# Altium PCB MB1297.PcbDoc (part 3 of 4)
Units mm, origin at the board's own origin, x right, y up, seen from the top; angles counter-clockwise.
Board outline 90.1 x 62.11 mm, 4 copper layers (Top Layer, GND, POWER+GND, Bottom Layer), stack 0.778 mm thick; 235 components, 175 nets, 1727 pads, 1 vias.
Unrouted connection lines stored in the file: 1.
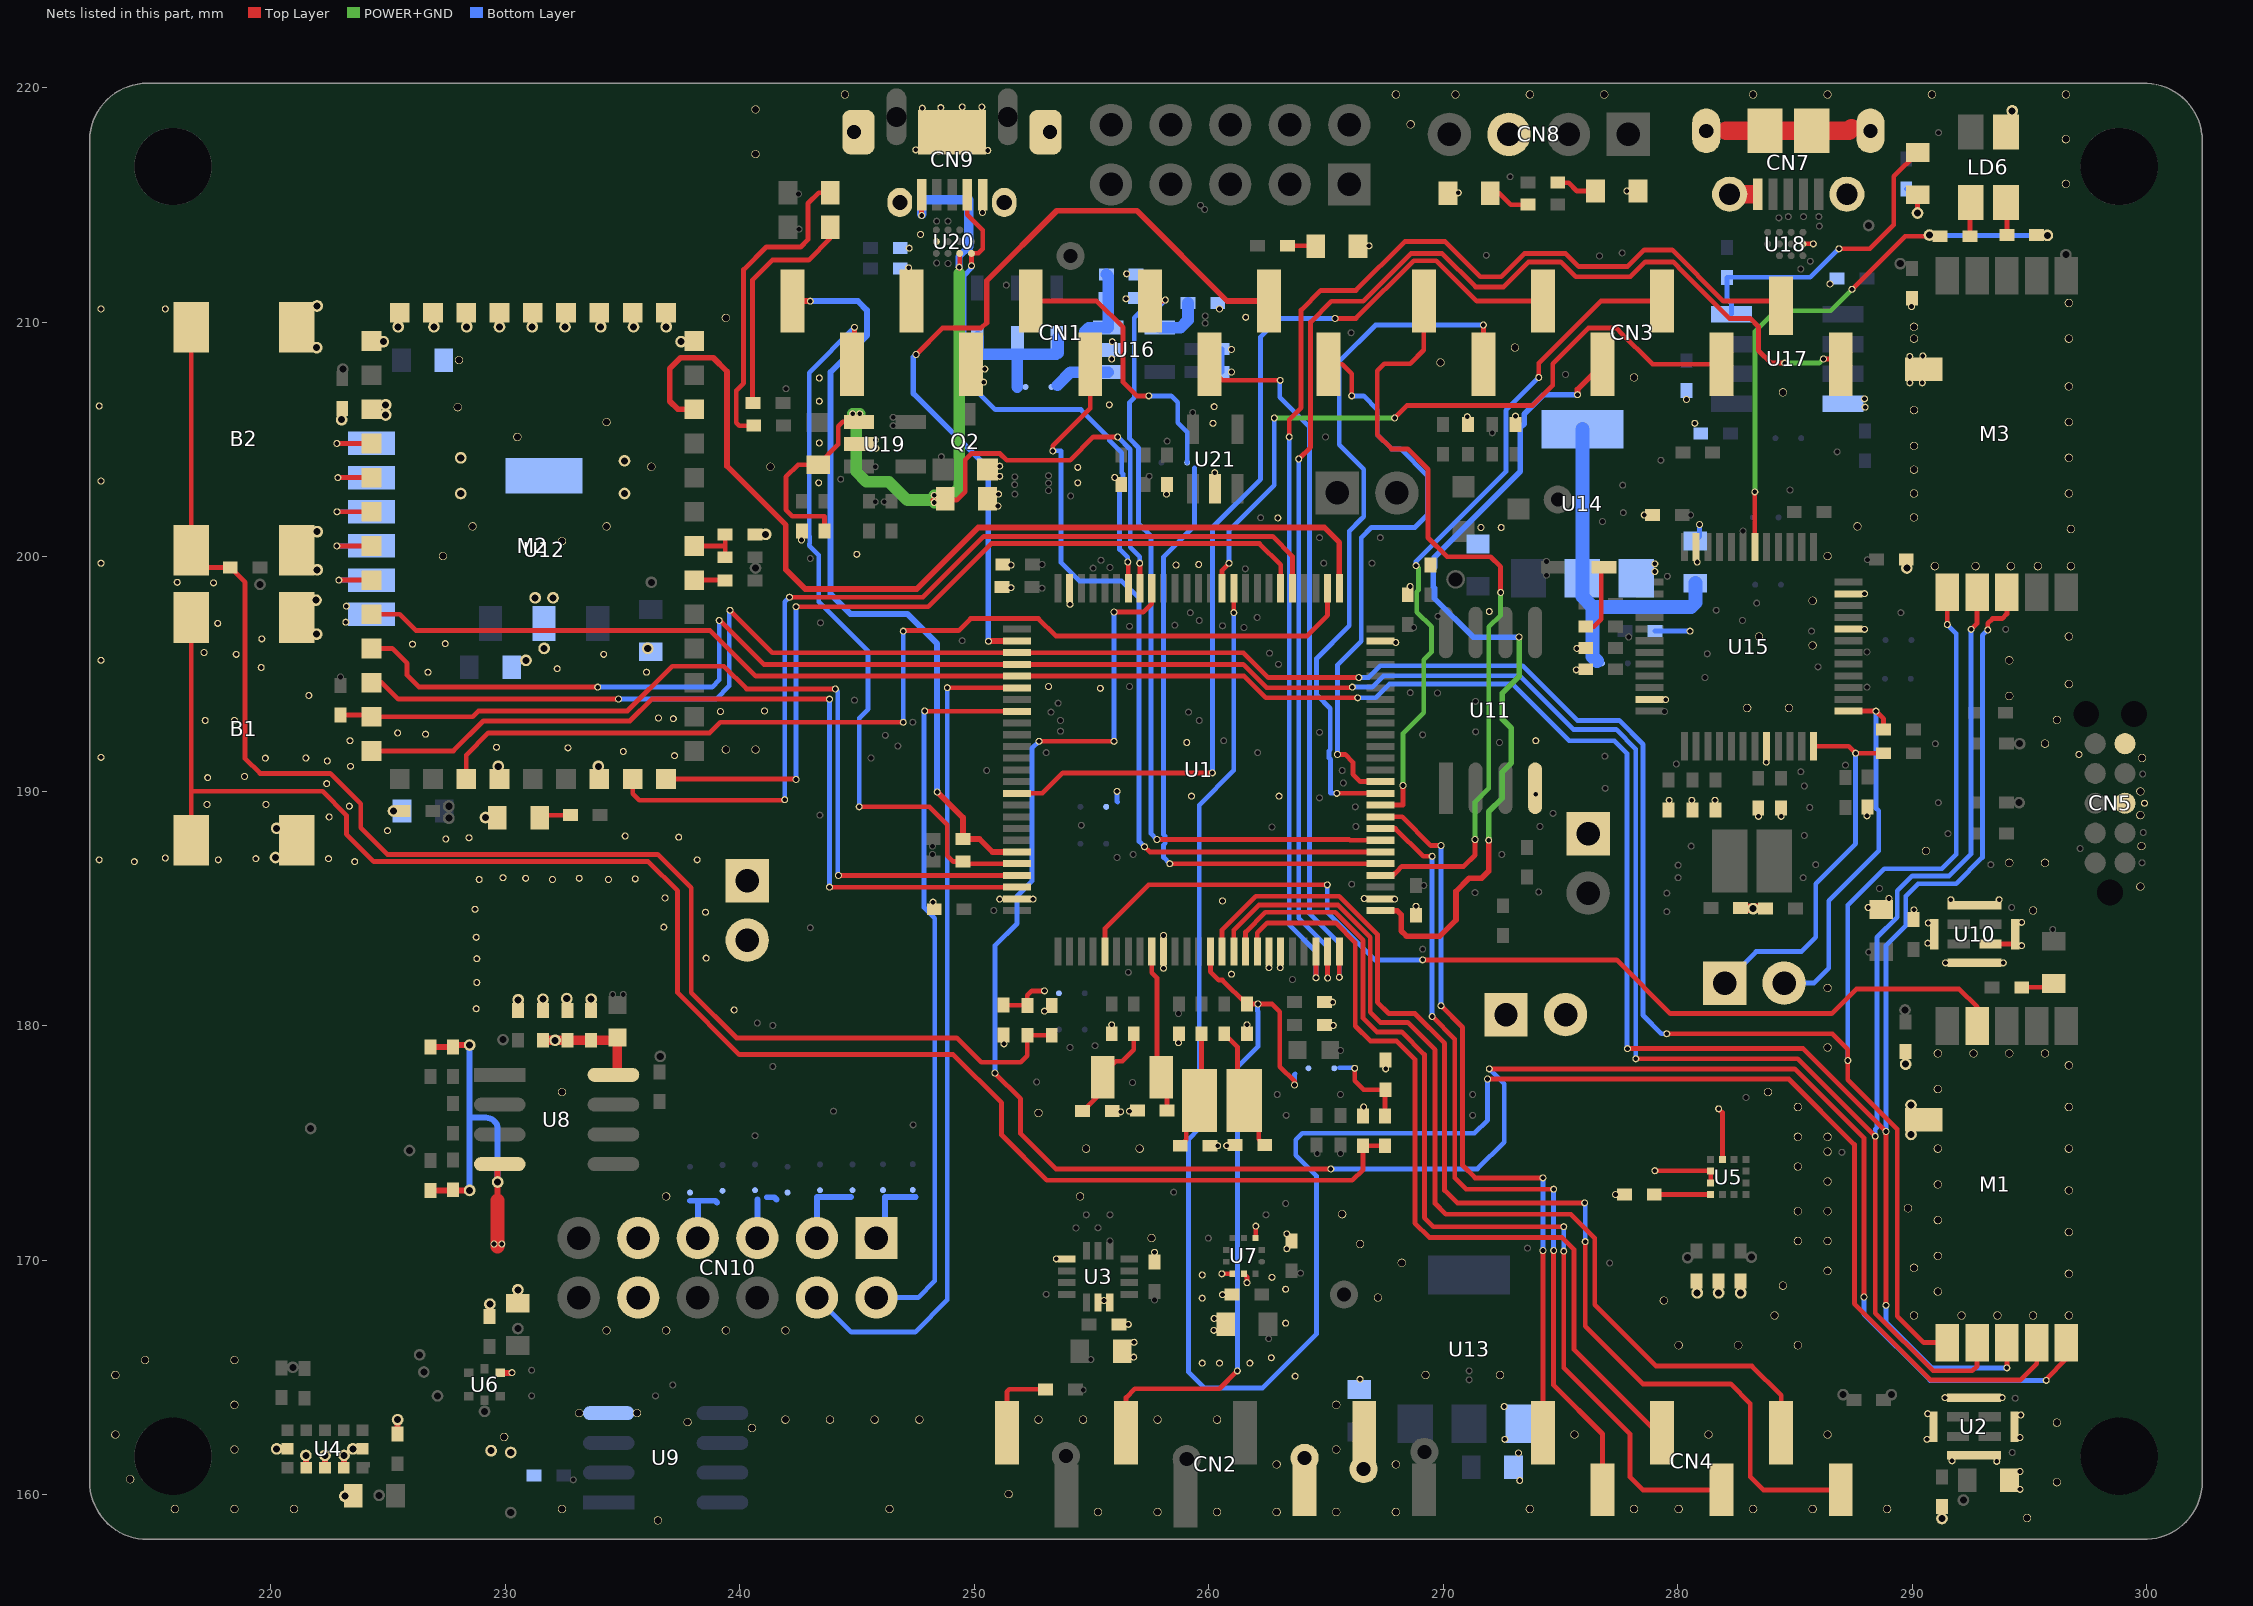
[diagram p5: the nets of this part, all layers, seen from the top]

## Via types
v1: diameter 0.4, hole 0.2, Top Layer to Bottom Layer, tented both sides, 1 vias

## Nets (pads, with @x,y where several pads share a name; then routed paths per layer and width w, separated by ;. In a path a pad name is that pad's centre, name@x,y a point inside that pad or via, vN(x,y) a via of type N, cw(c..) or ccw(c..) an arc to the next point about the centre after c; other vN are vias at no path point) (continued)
GND: B1.2 B2.2 C1.2 C2.2 C3.1 C4.2 C5.2 C6.1 C7.2 C8.1 C9.2 C10.2 C11.2 C12.2 C13.2 C14.2 C15.2 C16.2 C17.1 C18.2 C19.2 C20.2 C21.2 C22.2 C23.2 C24.2 C25.2 C26.2 C27.2 C28.2 C29.2 C30.2 C31.2 C32.2 C33.2 C34.2 C35.2 C36.2 C37.2 C38.2 C39.2 C40.2 C41.2 C42.2 C43.2 C44.2 C45.2 C46.2 C47.2 C48.2 C49.2 C50.2 C51.1 C52.1 C53.2 C54.2 C55.2 C56.2 C57.2 C58.2 C59.2 C60.2 C61.2 C62.2 C63.2 C64.2 C65.2 C66.2 C67.2 C68.2 C69.2 C71.2 C72.2 C73.2 C74.2 C75.2 C76.2 CN1.7 CN2.6 CN2.7 CN5.3 CN5.5 CN7.5 CN7.6 CN7.7 CN7.8 CN7.9 CN7.10 CN7.11 CN8.3 CN9.5 CN9.6 CN9.7 CN9.8 CN9.9 CN9.10 CN10.5 CN10.11 JP6.1 JP6.2 JP7.1 JP7.2 JP8.1 LD1.K LD2.K LD3.K LD5.K LD6.1 M1.6 M2.1 M2.3 M2.17 M2.20 M2.35 M2.36 M2.37 M2.38 M2.39 M2.40 M2.41 M2.42 M2.43 M2.44 M3.6 pad.0@212.75,210.566 pad.0@229.387,161.874 pad.1@215.494,210.566 pad.1@230.226,161.798 pad.2@212.674,187.071 pad.2@229.337,168.123 pad.2@230.53,168.732 pad.3@215.494,187.147 pad.3@229.146,188.874 pad.4@214.173,186.995 pad.5@212.75,191.44 pad.5@223.152,159.931 pad.5@279.476,193.904 pad.6@212.75,195.58 pad.6@223.215,197.891 pad.6@231.648,196.088 pad.6@287.96,198.425 pad.7@212.75,199.72 pad.7@223.19,197.206 pad.7@223.491,161.95 pad.7@231.267,198.247 pad.7@287.96,196.901 pad.8@212.75,203.225 pad.8@223.114,161.671 pad.8@232.029,198.247 pad.8@247.701,213.741 pad.8@283.769,191.237 pad.9@212.674,206.426 pad.9@222.301,161.671 pad.9@228.092,204.216 pad.10@217.551,198.882 pad.10@221.488,161.671 pad.10@228.092,202.692 pad.10@280.822,199.771 pad.11@216.002,198.907 pad.11@220.243,161.95 pad.11@235.077,204.089 pad.11@278.562,201.778 pad.12@217.729,197.155 pad.12@225.4,163.195 pad.12@235.077,202.692 pad.13@217.297,190.576 pad.14@218.872,190.627 pad.15@217.195,193.015 pad.15@275.692,196.088 pad.15@285.776,213.34 pad.16@218.44,193.015 pad.16@224.79,209.169 pad.16@275.666,195.174 pad.17@217.145,195.91 pad.17@225.425,209.804 pad.18@218.516,195.834 pad.18@226.949,209.804 pad.19@222.377,190.322 pad.19@228.346,209.804 pad.19@289.966,210.668 pad.20@223.342,189.357 pad.20@229.743,209.804 pad.21@217.754,187.071 pad.21@231.14,209.804 pad.22@219.354,187.122 pad.22@232.537,209.804 pad.23@217.272,189.433 pad.23@234.061,209.804 pad.24@219.786,189.433 pad.24@228.473,179.172 pad.24@235.458,209.804 pad.25@222.479,188.9 pad.25@228.473,172.974 pad.25@236.855,209.804 pad.26@222.453,187.122 pad.26@229.667,173.33 pad.26@237.49,209.169 pad.27@223.571,186.995 pad.27@230.543,181.102 pad.28@228.879,186.233 pad.28@231.597,181.127 pad.28@241.097,200.952 pad.29@228.752,180.721 pad.29@232.613,181.153 pad.29@247.218,213.157 pad.30@228.778,181.839 pad.30@233.655,181.127 pad.31@228.778,182.855 pad.32@228.752,183.769 pad.33@228.702,184.963 pad.34@229.895,186.309 pad.35@230.861,186.284 pad.36@232.004,186.233 pad.37@233.147,186.284 pad.37@260.553,169.418 pad.38@234.391,186.233 pad.38@261.62,169.037 pad.39@235.534,186.258 pad.39@291.262,158.979 pad.40@236.753,184.201 pad.41@236.804,185.445 pad.41@262.001,171.45 pad.42@224.968,188.316 pad.43@227.457,187.96 pad.43@260.579,168.529 pad.44@228.448,188.011 pad.44@260.223,167.513 pad.45@235.102,188.087 pad.45@260.21,167.005 pad.45@266.598,176.53 pad.45@299.898,189.484 pad.46@237.388,188.036 pad.46@267.538,178.156 pad.46@297.104,191.567 pad.47@238.176,187.071 pad.48@238.531,184.836 pad.48@264.083,161.568 pad.48@266.597,161.086 pad.49@238.557,182.88 pad.50@239.751,180.67 pad.50@256.807,166.497 pad.51@229.616,191.872 pad.51@256.794,165.862 pad.52@232.664,191.846 pad.52@256.565,167.259 pad.53@235.026,191.694 pad.54@237.211,191.516 pad.54@257.683,170.332 pad.55@236.525,193.116 pad.55@255.524,168.275 pad.55@256.083,189.992 pad.56@230.276,165.202 pad.56@237.16,193.091 pad.56@289.941,176.606 pad.57@229.845,170.688 pad.57@239.166,193.396 pad.57@253.492,170.053 pad.57@289.941,175.362 pad.58@229.514,170.688 pad.58@241.046,193.421 pad.58@289.712,178.359 pad.59@236.017,195.072 pad.59@266.827,213.258 pad.59@289.89,208.534 pad.60@232.207,195.224 pad.60@290.449,208.559 pad.61@234.188,195.834 pad.61@266.624,185.42 pad.61@289.89,207.416 pad.62@226.695,195.072 pad.62@267.919,185.395 pad.62@290.424,207.416 pad.63@227.432,196.291 pad.63@268.834,185.09 pad.63@280.365,206.705 pad.64@226.035,196.266 pad.64@256.489,212.065 pad.64@273.939,192.151 pad.64@280.721,205.689 pad.65@219.761,191.409 pad.65@256.464,210.998 pad.65@273.939,189.865 pad.65@287.96,206.731 pad.66 pad.67@221.615,194.081 pad.67@260.96,207.874 pad.68@219.583,195.275 pad.69@219.608,196.494 pad.69@262.56,182.474 pad.69@267.97,196.342 pad.70@222.402,191.287 pad.70@272.618,162.357 pad.70@280.822,168.605 pad.71@223.393,191.059 pad.71@272.593,163.754 pad.71@281.737,168.605 pad.72@223.368,192.151 pad.72@273.202,161.773 pad.72@282.677,168.605 pad.73@225.4,192.481 pad.73@273.253,160.604 pad.74@226.593,192.43 pad.74@272.466,201.244 pad.75@255.372,194.386 pad.75@271.602,201.244 pad.76@253.162,194.462 pad.76@288.112,185.039 pad.77@289.001,185.42 pad.78@290.068,184.937 pad.80@290.678,184.379 pad.81@289.763,199.517 pad.81@290.659,183.515 pad.82@247.777,219.126 pad.82@283.21,184.988 pad.82@291.643,185.369 pad.83@248.564,219.151 pad.83@293.7,185.369 pad.84@223.012,205.842 pad.84@250.317,219.177 pad.84@294.659,184.404 pad.85@224.892,206.477 pad.85@250.571,217.322 pad.85@294.659,183.413 pad.86@224.892,206.045 pad.86@247.498,217.348 pad.86@291.414,182.677 pad.87@249.479,219.177 pad.87@293.878,182.677 pad.88@230.873,195.58 pad.88@250.342,214.681 pad.89@236.068,196.088 pad.89@250.444,208.001 pad.89@291.389,164.135 pad.90@250.393,207.442 pad.90@293.827,164.135 pad.91@225.222,189.154 pad.91@279.019,173.812 pad.91@294.625,163.398 pad.92@229.692,191.059 pad.92@281.737,176.454 pad.92@294.589,162.433 pad.93@233.959,191.059 pad.93@251.257,179.222 pad.94@220.243,188.417 pad.94@252.984,180.619 pad.95@220.193,187.173 pad.95@290.652,163.449 pad.96 pad.97@221.945,196.698 pad.97@254.076,197.968 pad.97@291.694,161.442 pad.98 pad.99@221.971,199.441 pad.99@294.589,160.985 pad.100 pad.101@221.945,208.915 pad.101@266.446,164.922 pad.105@263.271,168.758 pad.106@263.271,167.31 pad.106@288.061,188.951 pad.107@262.687,169.266 pad.107@283.439,188.925 pad.107@294.259,219.011 pad.108@259.715,169.367 pad.108@284.404,188.925 pad.109@259.715,168.377 pad.109@281.584,189.611 pad.110@259.715,165.608 pad.110@280.594,189.611 pad.111@260.452,165.608 pad.111@279.629,189.611 pad.112@258.064,183.845 pad.112@261.747,165.608 pad.113@258.064,182.448 pad.113@262.661,165.837 pad.114 pad.115@260.96,182.194 pad.115@265.278,181 pad.116@260.579,185.318 pad.116@265.303,180.01 pad.117@262.992,189.789 pad.118 pad.119 pad.120 pad.121@255.854,180.035 pad.121@259.563,199.669 pad.122 pad.123 pad.124 pad.125 pad.126@260.172,205.689 pad.126@270.637,215.519 pad.127 pad.128@251.562,198.679 pad.128@261.569,210.21 pad.129@243.383,207.62 pad.130@243.383,206.629 pad.131@243.383,204.851 pad.132@243.357,203.149 pad.133@244.983,200.101 pad.136@251.079,185.395 pad.137@252.501,185.395 pad.142 pad.143@268.58,198.73 pad.149@277.343,172.796 pad.173 pad.175 pad.217 pad.218 pad.219 pad.222 pad.225 pad.226 pad.231 pad.232 pad.233 pad.234 pad.235 pad.236 pad.237 pad.249 pad.250 pad.251 pad.252 pad.253 pad.254 pad.255 pad.256 pad.257 pad.258 pad.259 pad.260 pad.261 pad.262 pad.263 pad.264 pad.265 pad.266 pad.267 pad.268 pad.269 pad.270 pad.271 pad.272 pad.273 pad.274 pad.275 pad.276 pad.277 pad.278 pad.279 pad.280 pad.281 pad.282 pad.283 pad.284 pad.285 pad.286 pad.287 pad.288 pad.289 pad.290 pad.291 pad.292 pad.293 pad.294 pad.295 pad.296 pad.297 pad.298 pad.299 pad.300 pad.301 pad.302 pad.303 pad.304 pad.305 pad.306 pad.307 pad.308 pad.309 pad.310 pad.311 pad.312 pad.313 pad.314 pad.315 pad.316 pad.317 pad.318 pad.319 pad.320 pad.321 pad.322 pad.327 pad.328 pad.329 pad.330 pad.331 pad.332 pad.333 pad.334 pad.335 pad.336 pad.337 pad.338 pad.339 pad.340 pad.341 pad.342 pad.343 pad.344 pad.345 pad.346 pad.347 pad.348 pad.349 pad.350 pad.351 pad.352 pad.353 pad.354 pad.355 pad.356 pad.357 pad.358 pad.359 pad.360 pad.361 pad.362 pad.363 pad.364 pad.365 pad.366 pad.367 pad.368 pad.369 pad.370 pad.371 pad.372 pad.373 pad.374 pad.375 pad.376 pad.377 pad.378 pad.379 pad.380 pad.381 pad.382 pad.383 pad.384 pad.385 pad.386 pad.387 pad.388 pad.389 pad.390 pad.391 pad.392 pad.393 pad.394 pad.395 pad.396 pad.397 pad.398 pad.399 pad.400 pad.401 pad.402 pad.403 pad.404 pad.405 pad.406 pad.407 pad.408 pad.409 pad.410 pad.411 pad.412 pad.413 pad.414 pad.415 pad.416 pad.417 pad.418 pad.420 pad.421 pad.422 pad.423 pad.424 pad.425 pad.426 pad.427 pad.428 pad.429 pad.430 pad.431 pad.432 pad.433 pad.434 Q2.2 R1.1 R27.2 R29.2 R31.2 R36.2 R38.1 R41.2 R46.1 R53.1 R54.2 R59.1 R64.2 SB13.1 TP6.1 U1.10 U1.19 U1.20 U1.27 U1.49 U1.74 U1.99 U2.5 U3.1 U3.6 U3.7 U4.2 U4.3 U4.4 U4.6 U4.12 U5.2 U5.3 U5.12 U6.5 U7.3 U7.8 U7.9 U8.4 U9.4 U10.2 U10.5 U11.4 U12.2 U13.1 U14.1 U15.8 U15.20 U15.23 U15.35 U15.47 U16.2 U17.4 U18.D2 U19.2 U20.D2 U21.2 | length 39.4
  Top Layer w0.2: U10.2@293.334,183.481 294.318,183.481 294.361,183.439 U10.5@294.361,183.481
  Top Layer w0.204: pad.37@260.553,169.418 U7.8@260.993,169.417 ; U7.9@261.493,169.417 261.62,169.29 pad.38@261.62,169.037 ; U7.3@261.993,170.943 pad.41@261.993,171.442 ; pad.91@279.019,173.812 281.397,173.812 U5.3@281.397,173.295 ; pad.92@281.737,176.454 281.897,176.293 U5.12@281.897,174.295 ; U18.D2@285.345,213.342 pad.15@285.713,213.342
  Top Layer w0.254: pad.11@220.243,161.95 U4.6@220.701,161.95 ; U4.4@221.488,161.163 pad.10@221.488,161.671 ; U4.3@222.301,161.15 pad.9@222.301,161.671 ; U4.2@223.114,161.163 pad.8@223.114,161.671 ; pad.7@223.491,161.95 U4.12@223.901,161.95 ; C22.2@225.4,162.585 pad.12@225.4,163.195 ; C72.2@226.797,172.974 pad.25@228.473,172.974 ; C69.2@226.797,179.095 C53.2@227.762,179.095 227.838,179.172 pad.24@228.473,179.172 ; pad.0@229.387,161.874 pad.0@229.393,161.869 ; 229.667,172.542 pad.26@229.667,173.33 229.667,173.875 cw(c229.973,173.875) U8.4@229.756,174.092 ; U6.5@229.783,165.194 230.268,165.194 pad.56@230.276,165.202
  Top Layer w0.4: C52.1@282.677,185.014 283.718,185.014 C51.1@283.743,184.988
  Top Layer w0.6: 229.667,170.586 229.667,172.542
  Top Layer w0.8: 282.067,218.161 287.299,218.161 287.401,218.262 ; CN7.7@282.209,215.458 283.159,215.458
  Bottom Layer w0.204: pad.55@256.083,189.992 256.083,189.56 256.108,189.535 ; C55.2@260.553,207.874 C59.2@260.553,208.864 ; C42.2@279.019,196.825 pad.222@280.518,196.825 ; C41.2@280.746,200.673 280.924,200.85 pad.217@280.924,201.371
  Bottom Layer w0.254: pad.25@228.473,172.974 228.473,176.073 ; pad.24@228.473,179.172 228.473,176.073 ; pad.26@229.667,173.33 229.667,175.614 ccw(c229.233,175.614) 229.54,175.92 ccw(c229.172,175.552) 229.172,176.073 228.473,176.073
LDO_3V3: C41.1 SB4.1 U14.2 U14.4 | length 15.4
  Bottom Layer w0.6: U14.4@275.924,205.435 U14.2@275.924,199.085 275.924,198.294 276.36,197.858 ; 276.555,195.555 276.36,195.75 276.36,197.858 ; C41.1@280.746,198.869 280.746,198.044 280.561,197.858 276.36,197.858
LED_STLINK: pad.18@283.282,202.764 pad.110@290.728,213.716 pad.111@295.758,213.703 pad.238 R44.1 R47.1 U15.30 | length 23.3
  Top Layer w0.204: U15.30@283.282,200.414 pad.18@283.282,202.764 ; pad.238@287.426,211.404 289.69,213.668 290.681,213.668 pad.110@290.728,213.716
  POWER+GND w0.204: pad.18@283.286,202.819 283.286,209.601 284.175,210.49 286.512,210.49 pad.238@287.426,211.404
  Bottom Layer w0.204: pad.110@290.728,213.716 290.741,213.703 pad.111@295.758,213.703
NetB1_1: B1.1 C35.1 R19.2 | length 73.2
  Top Layer w0.204: B1.1@216.596,187.909 216.596,189.992 ; B1.1@217.257,198.069 B1.1@216.596,197.409 216.596,189.992 ; R19.2@267.513,174.879 C35.1@266.573,174.879 266.573,173.863 266.116,173.406 253.086,173.406 251.155,175.336 251.155,176.708 249.098,178.765 239.979,178.765 237.338,181.407 237.338,185.75 236.093,186.995 224.384,186.995 223.215,188.163 223.215,188.976 222.199,189.992 216.596,189.992
NetB2_1: B2.1 C37.1 R23.1 R24.2 | length 63.9
  Top Layer w0.204: B2.1@216.596,209.779 B2.1@216.596,200.279 217.333,199.542 R23.1@218.262,199.542 218.897,198.907 218.897,191.389 219.532,190.754 222.529,190.754 223.825,189.459 223.825,188.443 224.967,187.301 236.498,187.301 237.922,185.877 237.922,181.407 239.852,179.476 249.25,179.476 250.292,178.435 251.968,178.435 252.256,178.723 R24.2@252.256,179.592 C37.1@253.298,179.592
NetC2_1: C2.1 R5.2 X1.2 | length 5.3
  Top Layer w0.204: C2.1@258.775,174.879 259.029,175.133 259.029,176.235 X1.2@259.603,176.809 ; X1.2@259.324,176.784 259.69,177.15 R5.2@259.69,179.654
NetC3_2: C3.2 CN2.3 pad.35@261.214,165.278 pad.36@262.09,180.924 pad.43@263.652,177.47 SB2.1 U1.14 | length 31.1
  Top Layer w0.204: CN2.3@256.465,162.642 256.465,164.136 256.845,164.516 260.452,164.516 pad.35@261.214,165.278 ; U1.14@260.063,183.156 260.063,182.304 260.425,181.941 260.578,181.941 261.596,180.924 C3.2@261.62,180.924 pad.36@262.09,180.924 262.56,180.924 262.687,180.924 263.018,180.593 263.018,178.256 263.652,177.622 pad.43@263.652,177.47
  Bottom Layer w0.204: pad.35@261.214,165.278 261.214,178.232 262.09,179.108 262.09,180.603 262.075,180.618 262.075,180.909 pad.36@262.09,180.924 ; pad.43@263.652,177.47 263.652,177.927 263.677,177.952
NetC4_1: C4.1 R7.2 X1.1 | length 5.4
  Top Layer w0.204: R7.2@260.655,179.654 261.224,179.085 X1.1@261.224,176.784 ; X1.1@261.503,176.809 262.128,176.185 262.128,175.158 C4.1@262.382,174.904
NetC14_1: C14.1 R12.2 X2.1 | length 4.4
  Top Layer w0.204: C14.1@254.61,176.352 255.468,177.21 X2.1@255.468,177.8 255.468,177.922 256.032,178.486 256.311,178.486 256.794,178.968 R12.2@256.794,179.654
NetC15_1: C15.1 U1.9 X2.2 | length 7
  Top Layer w0.204: U1.9@257.563,183.156 257.563,182.264 257.785,182.042 257.785,179.68 257.785,177.983 X2.2@257.968,177.8 258.216,177.551 C15.1@258.216,176.378
NetC23_1: C23.1 U5.4 | length 2.4
  Top Layer w0.204: C23.1@278.995,172.795 U5.4@281.397,172.795
NetC32_1: C32.1 C67.1 C68.1 L2.1 pad.31@232.118,179.375 U8.8 | length 4.6
  Top Layer w0.4: C67.1@231.597,179.375 C68.1@232.639,179.375 C32.1@233.655,179.375 234.658,179.375 L2.1@234.772,179.489 U8.8@234.772,178.067
NetC34_1: C34.1 pad.44@266.217,178.181 R19.1 SB2.2 | length 3.8
  Top Layer w0.204: pad.44@266.217,178.181 266.217,177.648 266.598,177.267 C34.1@267.538,177.267 267.513,177.241 R19.1@267.513,176.149
  Bottom Layer w0.204: 265.557,178.206 266.192,178.206 pad.44@266.217,178.181
NetC36_1: C36.1 pad.47@252.984,181.483 R24.1 SB3.2 | length 2.3
  Top Layer w0.204: C36.1@251.231,180.873 252.245,180.873 R24.1@252.256,180.862 252.256,181.289 252.451,181.483 pad.47@252.984,181.483
NetC56_1: C56.1 C57.1 SB10.1 U16.1 U16.3 | length 7.5
  Bottom Layer w0.5: 253.543,207.315 254.095,207.867 254.711,207.867 ; C56.1@255.626,212.039 255.712,211.953 U16.3@255.712,209.767 254.877,209.767 254.71,209.6 254.71,208.37 254.711,208.369 254.711,207.867 ; U16.1@255.712,207.867 254.711,207.867
NetC58_1: C58.1 U16.4 | length 2.1
  Bottom Layer w0.5: U16.4@257.912,209.767 258.789,209.767 259.105,210.083 C58.1@259.105,210.82
NetC66_1: C66.1 CN9.1 pad.0@247.747,214.554 pad.4@249.352,212.344 pad.20@245.11,206.096 pad.21@248.285,202.616 pad.22@248.285,202.311 pad.126@244.805,206.096 pad.179 pad.181 R57.1 R61.2 U1.68 U19.1 U20.B3 | length 49.7
  Top Layer w0.2: pad.4@249.373,212.289 U20.B3@249.373,212.936
  Top Layer w0.204: R57.1@243.606,201.092 243.606,201.727 242.24,201.727 241.96,202.006 241.96,203.403 242.481,203.924 R61.2@243.332,203.924 244.196,204.787 244.196,205.562 244.384,205.75 U19.1@245.077,205.75 ; pad.0@247.747,214.605 CN9.1@247.747,215.433 ; pad.22@248.234,202.413 249.25,202.413 249.606,202.768 249.606,204.14 249.865,204.399 251.09,204.399 251.375,204.114 254.076,204.114 255.067,205.105 pad.181@256.108,205.105 ; pad.179@257.048,199.72 257.063,199.706 U1.68@257.063,198.656
  POWER+GND w0.5: pad.126@244.805,206.096 pad.20@245.11,206.096 244.958,205.943 244.958,203.632 245.389,203.2 246.354,203.2 247.142,202.413 pad.22@248.285,202.413 ; pad.22@248.285,202.311 pad.22@248.285,202.413 ; pad.21@248.285,202.616 pad.22@248.285,202.413 ; 249.352,212.087 249.352,202.946 248.818,202.413 pad.22@248.285,202.413
  Bottom Layer w0.204: pad.181@256.108,205.105 256.643,204.57 256.643,203.208 256.642,203.206 256.642,200.406 257.048,200 pad.179@257.048,199.72
  Bottom Layer w0.3: pad.4@249.343,212.344 249.343,212.795 249.758,213.21
  Bottom Layer w0.4: pad.0@247.747,214.605 247.747,215.214 249.758,215.214 249.758,213.21
NetCN1_1: CN1.1 pad.58@266.09,206.858 pad.141@265.481,191.567 U1.37 | length 24.5
  Top Layer w0.204: CN1.1@265.101,208.202 265.686,208.202 266.09,207.797 pad.58@266.09,206.858 ; pad.141@265.481,191.567 265.811,191.567 266.141,191.237 266.141,190.729 266.463,190.406 U1.37@267.313,190.406
  Bottom Layer w0.204: pad.141@265.481,191.567 265.481,195.377 266.497,196.393 266.497,200.812 266.929,201.244 268.783,201.244 269.316,201.778 269.316,203.454 268.173,204.597 267.792,204.597 267.183,205.207 267.183,206.273 266.598,206.858 pad.58@266.09,206.858
NetCN1_2: CN1.2 pad.27@247.51,208.623 pad.95@250.596,196.393 U1.77 | length 35.1
  Top Layer w0.204: pad.27@247.51,208.623 248.643,209.756 250.294,209.756 250.52,209.982
  Top Layer w0.24: 250.52,209.982 250.52,211.76 253.513,214.753 256.925,214.753 260.776,210.902 CN1.2@262.561,210.902 ; pad.95@250.596,196.393 250.61,196.406 U1.77@251.813,196.406
  Bottom Layer w0.24: pad.27@247.51,208.623 247.396,208.509 247.396,206.959 250.596,203.759 pad.95@250.596,196.393
NetCN1_3: CN1.3 pad.23@263.041,207.52 pad.72@265.563,182.062 U1.25 | length 30.9
  Top Layer w0.204: CN1.3@260.021,208.076 260.577,207.52 pad.23@263.041,207.52 ; pad.72@265.563,182.062 U1.25@265.563,183.156
  Bottom Layer w0.204: pad.23@263.041,207.52 263.017,207.496 263.017,206.807 264.287,205.537 264.287,184.785 265.563,183.509 pad.72@265.563,182.062
NetCN1_4: CN1.4 pad.63@258.14,210.947 pad.83@257.785,187.936 U1.32 | length 34.7
  Top Layer w0.204: CN1.4@257.481,210.902 258.095,210.902 pad.63@258.14,210.947 ; pad.83@257.785,187.936 265.982,187.936 266.011,187.906 U1.32@267.313,187.906
  Bottom Layer w0.204: pad.83@257.785,187.936 257.531,188.19 257.531,200.863 256.997,201.397 256.997,204.649 256.616,205.03 256.616,206.578 256.819,206.781 256.819,210.185 257.051,210.417 257.61,210.417 pad.63@258.14,210.947
NetCN1_5: CN1.5 pad.38@253.344,204.509 pad.73@257.251,187.63 U1.31 | length 34.3
  Top Layer w0.204: pad.38@253.344,204.509 253.344,204.728 254.941,206.325 CN1.5@254.941,208.202 ; pad.73@257.251,187.63 257.475,187.406 U1.31@267.313,187.406
  Bottom Layer w0.204: pad.38@253.344,204.509 253.695,204.521 253.695,199.746 254.483,198.958 256.286,198.958 257.023,198.222 257.023,187.858 pad.73@257.251,187.63
NetCN1_6: CN1.6 pad.84@258.33,186.906 pad.171 SB1.1 U1.30 | length 38.7
  Top Layer w0.204: CN1.6@252.401,210.902 255.213,210.902 256.337,209.779 256.337,207.442 256.921,206.858 pad.171@257.438,206.858 ; pad.84@258.33,186.906 U1.30@267.313,186.906
  Bottom Layer w0.204: pad.171@257.438,206.858 258.394,206.858 258.674,206.578 258.674,205.715 259.072,205.316 SB1.1@259.072,204.013 ; pad.84@258.33,186.906 258.064,187.173 258.064,187.715 258.139,187.789 258.139,188.082 258.064,188.157 258.064,200 259.385,201.32 259.385,203.784
NetCN1_8: CN1.8 pad.28@247.193,212.319 R2.1
NetCN1_9: CN1.9 pad.108@245.085,189.332 pad.110@244.881,209.779 R8.2 U1.96 | length 32.6
  Top Layer w0.204: CN1.9@244.781,208.202 244.881,208.303 pad.110@244.881,209.779 ; pad.108@245.085,189.332 248.082,189.332 248.844,188.57 248.844,187.249 249.098,186.995 R8.2@249.504,186.995 ; R8.2@249.592,186.906 U1.96@251.813,186.906
  Top Layer w0.254: R8.2@249.504,186.995 R8.2@249.592,186.906
  Bottom Layer w0.204: pad.110@244.881,209.779 242.951,207.848 242.951,200.881 242.975,200.857 242.975,200.564 242.951,200.54 242.951,200.475 243.356,200.07 243.356,198.071 245.466,195.961 245.466,193.497 245.085,193.116 pad.108@245.085,189.332
NetCN1_10: CN1.10 pad.109@248.412,189.967 pad.111@243.002,210.896 R9.2 U1.95 | length 32.8
  Top Layer w0.254: CN1.10@242.241,210.902 242.996,210.902 pad.111@243.002,210.896 ; pad.109@248.412,189.967 249.504,188.874 R9.2@249.504,187.96 250.215,187.96 250.769,187.406 U1.95@251.813,187.406
  Bottom Layer w0.254: pad.111@243.002,210.896 245.034,210.896 245.415,210.515 245.415,209.423 243.865,207.874 243.865,198.399 244.704,197.561 247.142,197.561 248.412,196.291 pad.109@248.412,189.967
NetCN2_1: CN2.1 R3.2 | length 3.4
  Top Layer w0.204: CN2.1@251.385,162.642 251.385,164.39 251.485,164.49 R3.2@253.035,164.49
NetCN3_1: CN3.1 pad.25@263.83,204.165 pad.67@284.556,208.255 pad.69@286.207,208.432 pad.71@265.063,182.03 U1.24 | length 57.4
  Top Layer w0.204: pad.25@263.83,204.165 264.338,204.673 264.338,210.007 265.227,210.896 266.573,210.896 268.605,212.928 269.951,212.928 271.374,211.506 272.567,211.506 273.634,212.573 275.005,212.573 275.64,211.938 277.978,211.938 278.613,212.573 279.803,212.573 280.039,212.336 280.039,212.315 282.194,210.16 283.083,210.16 283.439,209.804 283.439,208.788 283.972,208.255 pad.67@284.556,208.255 ; pad.71@265.063,182.03 U1.24@265.063,183.156 ; pad.69@286.207,208.432 CN3.1@286.714,208.432
  POWER+GND w0.204: pad.67@284.556,208.255 286.029,208.255 pad.69@286.207,208.432
  Bottom Layer w0.204: pad.25@263.83,204.165 263.83,184.582 265.063,183.349 pad.71@265.063,182.03
NetCN3_2: CN3.2 pad.24@263.423,205.105 pad.70@264.566,182.042 U1.23 | length 54.4
  Top Layer w0.204: pad.24@263.423,205.105 263.423,205.842 263.931,206.35 263.931,210.515 264.77,211.353 266.268,211.353 268.351,213.436 270.078,213.436 271.577,211.938 272.466,211.938 273.456,212.928 275.209,212.928 275.768,212.369 277.851,212.369 278.562,213.081 279.756,213.081 281.934,210.902 CN3.2@284.405,210.902 ; U1.23@264.563,183.156 264.563,182.046 pad.70@264.566,182.042
  Bottom Layer w0.204: pad.24@263.423,205.105 263.423,184.302 264.566,183.159 pad.70@264.566,182.042
NetCN3_3: CN3.3 pad.202 pad.203 pad.204 U1.61 | length 30
  Top Layer w0.204: U1.61@260.563,198.656 260.563,199.425 pad.202@260.858,199.72 ; pad.204@267.919,205.918 268.453,206.451 273.812,206.451 274.663,207.303 274.663,208.229 276.19,209.756 277.379,209.756 277.499,209.636 277.499,209.622 278.919,208.202 CN3.3@281.865,208.202
  POWER+GND w0.204: pad.203@262.788,205.918 pad.204@267.919,205.918
  Bottom Layer w0.204: pad.202@260.858,199.72 260.858,201.117 262.788,203.048 pad.203@262.788,205.918
NetCN3_4: CN3.4 pad.224 pad.229 pad.230 U1.35 | length 29.2
  Top Layer w0.204: U1.35@267.313,189.406 268.276,189.406 pad.229@268.276,190.245 ; pad.224@274.066,207.645 274.066,208.255 276.713,210.902 CN3.4@279.325,210.902
  POWER+GND w0.204: pad.229@268.276,190.245 268.276,192.457 269.164,193.345 269.164,195.605 269.494,195.936 269.494,197.002 268.859,197.637 268.859,198.508 268.934,198.583 268.934,199.519 pad.230@268.834,199.619
  Bottom Layer w0.204: pad.230@268.834,199.593 pad.230@268.834,199.619 268.834,199.796 272.669,203.632 272.669,206.248 pad.224@274.066,207.645
NetCN3_5: CN3.5 pad.52@271.932,187.909 pad.223 pad.228 U1.26 | length 36.3
  Top Layer w0.24: U1.26@267.313,184.906 268.026,184.906 268.199,184.734 268.199,184.048 268.427,183.82 269.85,183.82 270.535,184.506 270.535,185.725 271.094,186.284 271.628,186.284 271.932,186.588 pad.52@271.932,187.909 ; pad.223@275.717,206.908 275.717,207.134 CN3.5@276.785,208.202
  POWER+GND w0.24: pad.52@271.932,187.909 271.932,189.128 272.517,189.713 272.517,190.83 272.898,191.211 272.898,192.684 272.517,193.065 272.517,194.183 273.228,194.894 pad.228@273.228,196.571
  Bottom Layer w0.24: pad.228@273.228,196.571 271.272,196.571 269.621,198.222 269.621,198.66 269.57,198.711 269.57,199.485 269.621,199.536 269.621,199.974 273.279,203.632 273.279,205.502 273.447,205.671 273.447,206.087 274.269,206.908 pad.223@275.717,206.908
NetCN3_6: CN3.6 pad.65@260.147,190.779 pad.75@265.379,210.16 U1.90 | length 42.2
  Top Layer w0.204: U1.90@251.813,189.906 252.898,189.906 253.771,190.779 pad.65@260.147,190.779 ; pad.75@265.379,210.16 266.269,210.16 268.732,212.622 269.698,212.622 271.419,210.902 CN3.6@274.245,210.902
  Bottom Layer w0.204: pad.65@260.147,190.779 260.147,201.244 262.204,203.302 262.204,209.372 262.992,210.16 pad.75@265.379,210.16
NetCN3_7: CN3.7 pad.57@271.704,209.88 pad.140@265.455,189.906 U1.36 | length 30.6
  Top Layer w0.204: pad.140@265.455,189.906 U1.36@267.313,189.906 ; pad.57@271.704,209.88 pad.57@271.704,209.88 CN3.7@271.705,208.202
  Bottom Layer w0.204: pad.140@265.455,189.906 265.185,189.906 265.185,191.362 265.127,191.42 265.127,191.713 265.175,191.761 265.175,193.525 264.593,194.107 264.593,195.657 265.989,197.053 265.989,201.092 266.485,201.588 ; 266.486,201.588 266.606,201.708 266.606,203.727 265.557,204.776 265.557,208.331 267.106,209.88 pad.57@271.704,209.88
NetCN3_8: CN3.8 pad.54@271.348,187.935 pad.55@272.44,198.476 U1.29 | length 33.6
  Top Layer w0.204: U1.29@267.313,186.406 267.851,186.406 268.117,186.672 268.117,186.684 268.224,186.792 270.866,186.792 271.348,187.274 pad.54@271.348,187.935 ; CN3.8@269.165,210.902 269.165,208.814 268.58,208.229 267.487,208.229 267.183,207.924 267.183,205.207 267.792,204.597 268.478,204.597 269.343,203.732 269.343,200.811 270.154,200 272.009,200 272.44,199.568 pad.55@272.44,198.476
  POWER+GND w0.204: pad.54@271.348,187.935 271.348,189.535 271.932,190.119 271.932,197.002 272.44,197.51 pad.55@272.44,198.476
NetCN4_1: CN4.1 pad.77@274.245,170.409 pad.81@274.245,173.506 pad.88@269.9,187.681 pad.90@269.9,180.848 U1.34 | length 31.6
  Top Layer w0.204: U1.34@267.313,188.906 268.243,188.906 269.469,187.681 pad.88@269.9,187.681 ; pad.90@269.9,180.848 270.815,179.934 270.815,174.041 271.349,173.506 pad.81@274.245,173.506 ; CN4.1@274.245,162.642 pad.77@274.245,170.409
  Bottom Layer w0.204: pad.90@269.9,180.924 pad.88@269.9,187.681 ; pad.81@274.245,173.506 pad.81@274.245,173.506 pad.77@274.245,170.409
NetCN4_2: CN4.2 pad.78@274.701,170.409 pad.82@274.701,173.025 pad.87@269.519,187.223 pad.89@269.519,180.391 U1.33 | length 34.9
  Top Layer w0.204: U1.33@267.313,188.406 267.955,188.406 269.138,187.223 pad.87@269.519,187.223 ; pad.89@269.519,180.391 270.485,179.426 270.485,173.507 270.967,173.025 pad.82@274.701,173.025 ; pad.78@274.701,170.409 274.701,164.668 276.785,162.584 CN4.2@276.785,160.202
  Bottom Layer w0.204: pad.89@269.519,180.391 pad.87@269.519,187.223 ; pad.78@274.701,170.409 pad.82@274.701,173.025 pad.82@274.726,173.025
NetCN4_3: CN4.3 U1.18 | length 35.9
  Top Layer w0.204: U1.18@262.063,183.156 262.063,183.958 262.484,184.379 265.405,184.379 266.243,183.54 266.243,179.984 266.878,179.349 267.995,179.349 268.783,178.562 268.783,171.577 269.392,170.967 275.057,170.967 275.565,170.459 275.565,166.192 279.115,162.642 CN4.3@279.325,162.642
NetCN4_4: CN4.4 pad.75@275.133,171.425 pad.76@275.133,170.383 U1.17 | length 42.3
  Top Layer w0.204: U1.17@261.563,183.156 261.563,183.991 262.406,184.835 265.381,184.835 266.573,183.643 266.573,180.315 267.157,179.73 268.224,179.73 269.189,178.765 269.189,171.806 269.57,171.425 pad.75@275.133,171.425 ; pad.76@275.133,170.383 275.133,165.405 277.952,162.585 277.952,160.757 278.507,160.202 CN4.4@281.865,160.202
  Bottom Layer w0.204: pad.76@275.133,170.383 pad.75@275.133,171.425
NetCN4_5: CN4.5 U1.16 | length 42.3
  Top Layer w0.204: U1.16@261.063,183.156 261.063,184.075 262.128,185.141 265.508,185.141 266.879,183.77 266.879,180.567 267.31,180.137 268.478,180.137 269.646,178.968 269.646,172.415 270.104,171.958 275.438,171.958 276.454,170.942 276.454,168.097 279.07,165.481 283.159,165.481 284.405,164.235 CN4.5@284.405,162.642
NetCN4_6: CN4.6 pad.79@276.047,170.79 pad.80@276.022,172.441 U1.15 | length 48.7
  Top Layer w0.204: U1.15@260.563,183.156 260.563,184.083 262.001,185.522 265.56,185.522 267.185,183.896 267.185,180.998 267.665,180.518 268.783,180.518 270.053,179.248 270.053,172.974 270.586,172.441 pad.80@276.022,172.441 ; pad.79@276.047,170.79 276.047,167.183 278.511,164.719 282.245,164.719 283.083,163.881 283.083,160.757 283.638,160.202 CN4.6@286.945,160.202
  Bottom Layer w0.204: pad.80@276.022,172.441 276.047,172.415 pad.79@276.047,170.79
NetCN6_1: CN6.1 pad.102@287.579,191.618 R42.1 U15.12 | length 16.4
  Top Layer w0.204: U15.12@285.782,191.914 287.282,191.914 pad.102@287.579,191.618 R42.1@288.773,191.618
  Bottom Layer w0.204: CN6.1@281.991,181.813 283.337,183.159 285.267,183.159 285.877,183.769 285.877,186.055 287.579,187.757 pad.102@287.579,191.618
NetCN6_2: CN6.2 pad.103@288.449,193.414 R43.1 U15.13 | length 16.1
  Top Layer w0.204: U15.13@287.282,193.414 pad.103@288.449,193.414 288.773,193.091 R43.1@288.773,192.634
  Bottom Layer w0.204: CN6.2@284.531,181.813 285.801,181.813 286.436,182.448 286.436,185.318 288.566,187.449 288.566,189.164 288.449,189.281 pad.103@288.449,193.414
NetCN9_4: CN9.4 pad.5@249.873,212.407 pad.180 U1.69 U20.A3 | length 22.7
  Top Layer w0.204: CN9.4@249.697,215.433 249.697,214.59 250.358,213.929 250.358,213.125 250.169,212.936 U20.A3@249.873,212.936 pad.5@249.873,212.407 ; pad.180@256.54,199.771 256.563,199.748 U1.69@256.563,198.656
  Bottom Layer w0.204: pad.5@249.873,212.407 249.873,212.307 249.555,211.988 249.555,207.602 250.884,206.273 254.541,206.273 255.754,205.06 255.754,204.958 256.286,204.427 256.286,203.574 256.335,203.524 256.335,203.231 256.191,203.087 256.191,200.298 256.209,200.298 256.54,199.967 pad.180@256.54,199.771
NetCN10_1: CN10.1 SB14.1 SB19.1 | length 3.2
  Bottom Layer w0.254: CN10.1@245.821,170.942 246.177,171.298 246.177,172.695 247.498,172.695
NetCN10_2: CN10.2 SB12.1 SB15.1 | length 3.8
  Bottom Layer w0.254: CN10.2@242.849,171.374 CN10.2@243.281,170.942 243.281,172.695 244.729,172.695
NetCN10_3: CN10.3 SB18.1 SB20.2 | length 2.1
  Bottom Layer w0.254: CN10.3@240.741,170.942 240.741,172.593 ; 241.143,172.682 241.465,172.682 241.554,172.593
NetCN10_4: CN10.4 SB16.1 SB21.2 | length 2.7
  Bottom Layer w0.254: 237.871,172.532 238.948,172.532 239.014,172.466 ; CN10.4@238.201,170.942 238.201,172.466
NetCN10_7: CN10.7 pad.143@247.879,193.421 U1.83 | length 31.2
  Top Layer w0.204: pad.143@247.864,193.406 U1.83@251.813,193.406
  Bottom Layer w0.204: CN10.7@245.821,168.402 247.599,168.402 248.31,169.113 248.31,184.582 247.853,185.039 247.853,193.396 pad.143@247.879,193.421
NetCN10_8: CN10.8 pad.144@248.844,194.412 U1.81 | length 35.8
  Top Layer w0.204: pad.144@248.844,194.412 248.849,194.406 U1.81@251.813,194.406
  Bottom Layer w0.204: CN10.8@243.281,168.402 244.754,166.929 247.472,166.929 248.844,168.3 pad.144@248.844,194.412
NetD2_2: D2.2 R28.1 | length 3
  Top Layer w0.204: R28.1@276.073,197.028 276.428,197.028 276.733,197.333 276.733,199.43 D2.2@276.845,199.542
NetD3_2: D3.2 D4.2 D5.2 SB10.2 | length 6.2
  Bottom Layer w0.5: D4.2@250.139,209.369 250.139,208.636 253.492,208.636 253.568,208.712 ; 251.825,207.239 251.825,208.594 ; 253.568,208.686 D3.2@253.568,209.344
NetLD1_A: LD1.A R18.2 | length 1.8
  Top Layer w0.204: LD1.A@271.996,215.494 272.39,215.494 272.872,215.011 R18.2@273.609,215.011
NetLD2_A: LD2.A R20.2 | length 1.8
  Top Layer w0.204: R20.2@274.879,215.951 275.336,215.951 275.692,215.595 LD2.A@276.492,215.595
NetLD3_A: LD3.A R21.2 | length 1.4
  Top Layer w0.204: LD3.A@231.457,188.874 231.559,188.976 R21.2@232.766,188.976
NetLD4_K: LD4.K R22.2 | length 1.4
  Top Layer w0.204: R22.2@294.665,181.635 295.872,181.635 LD4.K@296.037,181.8
NetLD5_A: LD5.A R25.2 | length 1.2
  Top Layer w0.204: R25.2@263.347,213.258 264.528,213.258 LD5.A@264.554,213.233
NetLD6_2: LD6.2 R44.2 | length 1.4
  Top Layer w0.204: LD6.2@293.993,215.111 294.03,215.074 R44.2@294.03,213.716
NetLD6_3: LD6.3 R47.2 | length 1.5
  Top Layer w0.204: R47.2@292.456,213.665 292.456,215.074 LD6.3@292.493,215.111
NetLD7_A: LD7.A pad.1@290.22,214.655 R52.1 | length 2
  Top Layer w0.204: pad.1@290.22,214.655 LD7.A@290.22,215.43
  Bottom Layer w0.204: R52.1@289.738,215.684 290.22,215.201 pad.1@290.22,214.655
NetLD7_K: LD7.K pad.74@286.868,213.131 R49.1 U17.8 | length 13.2
  Top Layer w0.204: pad.74@286.868,213.131 288.188,213.131 289.204,214.147 289.204,216.218 LD7.K@290.22,217.233
  Bottom Layer w0.204: U17.8@282.283,210.337 282.283,210.807 282.092,210.998 R49.1@282.092,211.912 285.648,211.912 pad.74@286.868,213.131
NetLD8_K: LD8.K R56.2 | length 9.8
  Top Layer w0.204: R56.2@240.563,206.553 240.538,206.578 240.538,211.811 241.375,212.647 242.924,212.647 243.853,213.576 LD8.K@243.853,214.046
NetLD9_K: LD9.K R55.2 | length 13.4
  Top Layer w0.204: R55.2@240.589,205.588 239.979,205.588 239.846,205.721 239.846,207.086 240.157,207.397 240.157,212.242 241.122,213.207 242.595,213.207 242.9,213.512 242.9,215.062 243.357,215.519 LD9.K@243.853,215.519
NetM1_4: M1.4 pad.85@265.049,186.004 pad.92@269.113,182.804 U1.5 | length 43.5
  Top Layer w0.204: U1.5@255.563,183.156 255.563,184.138 257.429,186.004 pad.85@265.049,186.004 ; pad.92@269.113,182.804 277.393,182.804 279.684,180.513 286.558,180.513 287.604,181.559 291.998,181.559 292.76,180.797 M1.4@292.76,179.984
  Bottom Layer w0.204: pad.85@265.049,186.004 265.049,184.836 267.081,182.804 pad.92@269.113,182.804
NetM1_7: M1.7 M2.11 M3.7 pad.42@279.527,179.654 pad.137@266.395,194.843 pad.150@239.573,197.714 pad.154 pad.160 pad.169 U1.78 | length 120
  Top Layer w0.204: M2.11@224.285,194.629 224.725,194.629 225.425,193.929 pad.154@234.823,193.929 ; pad.150@239.573,197.714 241.38,195.906 U1.78@251.813,195.906 261.471,195.906 262.534,194.843 pad.137@266.395,194.843 ; pad.42@279.527,179.654 286.588,179.654 287.249,178.994 pad.169@287.249,178.511 287.249,177.698 289.357,175.59 289.357,167.615 290.487,166.484 M1.7@291.49,166.484 ; pad.160@291.49,197.104 M3.7@291.49,198.488
  Bottom Layer w0.204: pad.154@234.823,193.929 238.989,193.929 239.547,194.488 239.547,197.688 pad.150@239.573,197.714 ; pad.137@266.395,194.843 266.802,194.843 267.31,195.351 273.38,195.351 275.717,193.015 277.495,193.015 278.512,191.997 278.512,180.442 279.3,179.654 pad.42@279.527,179.654 ; pad.169@287.249,178.511 287.249,185.141 288.798,186.69 291.262,186.69 291.871,187.3 291.871,196.723 pad.160@291.49,197.104
NetM1_8: M1.8 M2.10 M3.8 pad.21@292.506,196.901 pad.25@288.417,175.285 pad.44@278.206,178.587 pad.138 pad.149@239.116,197.282 pad.153@233.934,194.437 U1.79 | length 125
  Top Layer w0.204: M2.10@224.285,196.086 224.283,196.088 225.171,196.088 225.806,195.453 225.806,194.945 226.314,194.437 pad.153@233.934,194.437 ; pad.149@239.116,197.307 241.016,195.406 U1.79@251.813,195.406 261.463,195.406 262.458,194.412 pad.138@266.116,194.412 ; pad.44@278.206,178.587 285.115,178.587 pad.25@288.417,175.285 288.417,167.742 290.881,165.278 292.557,165.278 292.76,165.481 M1.8@292.76,166.484 ; pad.21@292.506,196.901 292.76,197.155 M3.8@292.76,198.488
  Bottom Layer w0.204: pad.153@233.934,194.437 238.811,194.437 239.116,194.742 pad.149@239.116,197.282 ; pad.138@266.116,194.437 266.967,194.437 267.45,194.92 273.253,194.92 275.539,192.634 277.368,192.634 278.206,191.795 pad.44@278.206,178.587 ; pad.25@288.417,175.285 288.417,175.59 288.492,175.665 288.492,183.767 289.355,184.631 289.355,185.749 289.991,186.384 291.565,186.384 292.506,187.325 pad.21@292.506,196.901
NetM1_9: M1.9 M2.9 M3.9 pad.22@293.218,196.875 pad.27@288.874,175.489 pad.43@277.851,179.019 pad.139 pad.161 pad.163 U1.80 | length 123.1
  Top Layer w0.204: M2.9@224.285,197.543 225.494,197.543 226.187,196.85 238.735,196.85 240.678,194.906 U1.80@251.813,194.906 261.506,194.906 262.433,193.98 pad.139@266.344,193.98 ; pad.43@277.851,179.019 285.344,179.019 pad.27@288.874,175.489 pad.161@288.874,168.072 ; pad.22@293.218,196.875 293.218,197.155 293.421,197.358 293.827,197.358 294.03,197.561 M3.9@294.03,198.488 ; pad.163@294.03,165.405 M1.9@294.03,166.484
  Bottom Layer w0.204: pad.139@266.344,193.98 267.106,193.98 267.691,194.564 272.948,194.564 275.361,192.151 277.292,192.151 277.825,191.618 pad.43@277.825,179.019 ; pad.161@288.874,168.072 288.874,167.361 290.83,165.405 pad.163@294.03,165.405 ; pad.27@288.874,175.489 288.874,183.413 289.714,184.253 289.714,185.523 290.246,186.055 291.872,186.055 292.989,187.172 292.989,196.647 pad.22@293.218,196.875
NetM1_10: M1.10 pad.198 pad.199 U1.60 | length 93.8
  Top Layer w0.204: pad.198@261.063,197.613 U1.60@261.063,198.656 ; pad.199@271.882,177.724 284.734,177.724 287.528,174.93 287.528,168.148 290.794,164.882 294.6,164.882 295.3,165.583 M1.10@295.3,166.484
  Bottom Layer w0.204: pad.198@261.063,197.613 261.063,190.882 259.589,189.409 259.589,175.615 259.131,175.156 259.131,165.227 259.817,164.541 262.28,164.541 264.592,166.853 264.592,173.584 263.703,174.473 263.703,175.133 263.982,175.412 271.323,175.412 271.882,175.971 pad.199@271.882,177.724
NetM1_11: M1.11 pad.162 pad.164 pad.191 pad.192 pad.194 pad.195 pad.196 pad.197 U1.67 | length 89.8
  Top Layer w0.204: pad.197@250.875,177.978 251.968,176.885 251.968,175.387 253.467,173.888 pad.196@265.201,173.888 ; pad.194@252.755,192.126 pad.192@255.956,192.126 ; pad.191@255.956,197.637 257.2,197.637 257.563,198 U1.67@257.563,198.656 ; pad.195@271.958,178.156 284.988,178.156 287.934,175.209 pad.164@287.934,168.427 ; pad.162@295.707,164.922 296.57,165.786 M1.11@296.57,166.484
  Bottom Layer w0.204: pad.197@250.875,177.978 250.875,183.413 251.816,184.353 251.816,185.522 252.451,186.157 252.451,191.821 pad.194@252.755,192.126 ; pad.192@255.956,192.126 pad.191@255.956,197.637 ; pad.196@265.201,173.888 271.45,173.888 272.593,175.031 272.593,177.521 pad.195@271.958,178.156 ; pad.164@287.934,168.427 287.934,167.691 290.754,164.871 pad.162@295.707,164.871
NetM2_4: M2.4 pad.1@222.811,204.828 TP1.1 | length 3
  Top Layer w0.204: pad.1@222.811,204.828 M2.4@224.285,204.828
  Bottom Layer w0.204: pad.1@222.811,204.828 TP1.1@224.291,204.828
NetM2_5: M2.5 pad.2@222.853,203.371 TP2.1 | length 2.9
  Top Layer w0.204: pad.2@222.853,203.371 M2.5@224.285,203.371
  Bottom Layer w0.204: pad.2@222.853,203.371 TP2.1@224.291,203.371
NetM2_6: M2.6 pad.3@222.818,201.914 TP3.1 | length 2.9
  Top Layer w0.204: pad.3@222.818,201.914 M2.6@224.285,201.914
  Bottom Layer w0.204: pad.3@222.818,201.914 TP3.1@224.291,201.914
NetM2_7: M2.7 pad.4@222.809,200.457 TP4.1 | length 3
  Top Layer w0.204: pad.4@222.809,200.457 M2.7@224.285,200.457
  Bottom Layer w0.204: pad.4@222.809,200.457 TP4.1@224.291,200.457
NetM2_8: M2.8 pad.5@222.894,199 TP5.1 | length 2.8
  Top Layer w0.204: pad.5@222.894,199 M2.8@224.285,199
  Bottom Layer w0.204: pad.5@222.894,199 TP5.1@224.291,199
NetM2_12: M2.12 pad.145@244.2,186.406 pad.147 R26.1 U1.97 | length 38.1
  Top Layer w0.204: R26.1@222.961,193.243 224.214,193.243 M2.12@224.285,193.172 228.605,193.172 228.854,193.421 235.204,193.421 237.109,195.326 239.319,195.326 240.284,194.361 pad.147@244.069,194.361 ; pad.145@244.2,186.406 U1.97@251.813,186.406
  Bottom Layer w0.204: pad.147@244.069,194.361 244.172,194.257 244.172,186.434 pad.145@244.2,186.406
NetM2_13: M2.13 pad.146@243.818,185.906 pad.148 U1.98 | length 36.5
  Top Layer w0.204: M2.13@224.285,191.715 227.783,191.715 229.062,192.994 235.311,192.994 236.245,193.929 pad.148@243.815,193.929 ; pad.146@243.818,185.906 U1.98@251.813,185.906
  Bottom Layer w0.204: pad.146@243.818,185.906 pad.148@243.818,193.925
NetM2_16: M2.16 pad.152@246.964,192.938 pad.155@246.964,196.825 U1.52 | length 44.3
  Top Layer w0.204: M2.16@228.325,190.515 228.325,191.537 229.27,192.481 238.709,192.481 239.166,192.938 pad.152@246.964,192.938 ; pad.155@246.964,196.825 246.99,196.85 249.326,196.85 249.834,197.358 252.73,197.358 253.465,196.623 264.187,196.623 265.063,197.499 U1.52@265.063,198.656
  Bottom Layer w0.204: pad.152@246.964,192.938 pad.155@246.964,196.825
NetM2_21: M2.21 pad.101@242.113,198.272 pad.104@241.91,189.636 U1.55 | length 40.2
  Top Layer w0.204: M2.21@235.425,190.515 235.425,189.898 235.712,189.611 pad.104@241.91,189.611 ; pad.101@242.113,198.272 247.802,198.272 250.393,200.863 262.712,200.863 263.563,200.013 U1.55@263.563,198.656
  Bottom Layer w0.204: pad.104@241.91,189.636 241.91,198.069 pad.101@242.113,198.272
NetM2_22: M2.22 pad.102@242.392,197.866 pad.103@242.392,190.5 U1.56 | length 36.1
  Top Layer w0.204: M2.22@236.845,190.515 pad.103@242.392,190.515 ; pad.102@242.392,197.866 248.031,197.866 250.722,200.557 262.155,200.557 263.063,199.649 U1.56@263.063,198.656
  Bottom Layer w0.204: pad.103@242.392,190.5 pad.102@242.392,197.866
NetM2_28: M2.28 R66.1 | length 1.3
  Top Layer w0.204: M2.28@238.045,199 R66.1@239.353,199
NetM2_29: M2.29 R64.1 R65.1 | length 2.3
  Top Layer w0.204: M2.29@238.045,200.457 239.37,200.457 ; R65.1@239.37,199.974 239.37,200.457 ; R64.1@239.37,200.939 239.37,200.457
NetM2_33: M2.33 U1.51 | length 42.2
  Top Layer w0.24: M2.33@238.045,206.285 237.352,206.285 237.007,206.629 237.007,208.026 237.465,208.483 238.862,208.483 239.446,207.899 239.446,203.86 241.96,201.346 241.96,199.441 242.782,198.619 247.539,198.619 250.165,201.244 264.922,201.244 265.563,200.604 U1.51@265.563,198.656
